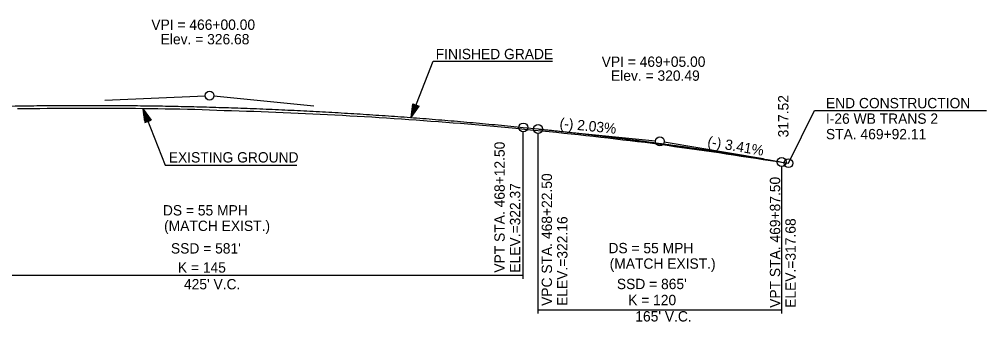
# Model space of a CAD drawing. Extents: x 69 to 2003113, y 512 to 837401.
# Drawn here: x 1924834 to 1925489, y 831485 to 831689 of the extents above; entities that cross this region are included whole.
import ezdxf

# ---------------------------------------------------------------- set-up
doc = ezdxf.new("R2010")
doc.units = 0
for name, color, linetype in [('BR_CENTER LINE BASELINE', 7, 'Continuous'), ('BR_CONCRETE', 7, 'Continuous'), ('BR_GRID DOTS', 7, 'Continuous'), ('BR_GRID LINES', 7, 'Continuous'), ('BR_TEXT', 7, 'Continuous'), ('RD_PD_ALT1_TrvlWay', 7, 'Continuous'), ('RD_SHT_IplotShp', 7, 'Continuous')]:
    doc.layers.add(name, color=color, linetype=linetype)

msp = doc.modelspace()

# ---------------------------------------------------------------- linework, layer by layer
at = {"layer": 'BR_CENTER LINE BASELINE'}
for p, q in [((1924892.19, 831634.52), (1924960.13, 831637.56)), ((1925033.76, 831630.53), (1924966.11, 831637.39)), ((1925197.49, 831613.92), (1925265.14, 831607.05)), ((1925338.11, 831594.82), (1925271.08, 831606.24))]:
    msp.add_line(p, q, dxfattribs=at)
for centre in [(1924963.12, 831637.7), (1925268.12, 831606.75), (1925355.23, 831591.9)]:
    msp.add_circle(centre, 3, dxfattribs=at)
at = {"layer": 'BR_GRID DOTS'}
for p, q in [((1925175.62, 831513.63), (1925175.62, 831613.13)), ((1925185.62, 831490.19), (1925185.62, 831612.12)), ((1925350.62, 831490.19), (1925350.62, 831589.69)), ((1924750.62, 831516.13), (1925175.62, 831516.13)), ((1925185.62, 831492.69), (1925350.62, 831492.69))]:
    msp.add_line(p, q, dxfattribs=at)
msp.add_lwpolyline([(1925355.19, 831591.9), (1925372.79, 831627.51), (1925489.44, 831627.51)], dxfattribs=at)
for centre in [(1925175.62, 831616.13), (1925185.62, 831615.12), (1925350.62, 831592.69)]:
    msp.add_circle(centre, 3, dxfattribs=at)
at = {"layer": 'BR_GRID LINES'}
for p, q in [((1925175.62, 831616.13), (1925185.62, 831615.12)), ((1925350.62, 831592.69), (1925355.23, 831591.9))]:
    msp.add_line(p, q, dxfattribs=at)
for points in [[(1924750.62, 831628.18), (1924759.12, 831628.54), (1924767.62, 831628.89), (1924776.12, 831629.21), (1924784.62, 831629.5), (1924793.12, 831629.77), (1924801.62, 831630.01), (1924810.12, 831630.23), (1924818.62, 831630.43), (1924827.12, 831630.6), (1924835.62, 831630.74), (1924844.12, 831630.86), (1924852.62, 831630.96), (1924861.12, 831631.03), (1924869.62, 831631.07), (1924878.12, 831631.09), (1924886.62, 831631.09), (1924895.12, 831631.06), (1924903.62, 831631), (1924912.12, 831630.92), (1924920.62, 831630.82), (1924929.12, 831630.69), (1924937.62, 831630.54), (1924946.12, 831630.36), (1924954.62, 831630.15), (1924963.12, 831629.93), (1924971.62, 831629.67), (1924980.12, 831629.39), (1924988.62, 831629.09), (1924997.12, 831628.76), (1925005.62, 831628.41), (1925014.12, 831628.03), (1925022.62, 831627.63), (1925031.12, 831627.2), (1925039.62, 831626.75), (1925048.12, 831626.27), (1925056.62, 831625.77), (1925065.12, 831625.24), (1925073.62, 831624.69), (1925082.12, 831624.12), (1925090.62, 831623.52), (1925099.12, 831622.89), (1925107.62, 831622.24), (1925116.12, 831621.56), (1925124.62, 831620.86), (1925133.12, 831620.14), (1925141.62, 831619.38), (1925150.12, 831618.61), (1925158.62, 831617.81), (1925167.12, 831616.98), (1925175.62, 831616.13)], [(1925185.62, 831615.12), (1925188.92, 831614.78), (1925192.22, 831614.44), (1925195.52, 831614.09), (1925198.82, 831613.74), (1925202.12, 831613.39), (1925205.42, 831613.03), (1925208.72, 831612.66), (1925212.02, 831612.29), (1925215.32, 831611.92), (1925218.62, 831611.54), (1925221.92, 831611.16), (1925225.22, 831610.77), (1925228.52, 831610.38), (1925231.82, 831609.99), (1925235.12, 831609.58), (1925238.42, 831609.18), (1925241.72, 831608.77), (1925245.02, 831608.35), (1925248.32, 831607.94), (1925251.62, 831607.51), (1925254.92, 831607.08), (1925258.22, 831606.65), (1925261.52, 831606.21), (1925264.82, 831605.77), (1925268.12, 831605.33), (1925271.42, 831604.88), (1925274.72, 831604.42), (1925278.02, 831603.96), (1925281.32, 831603.5), (1925284.62, 831603.03), (1925287.92, 831602.55), (1925291.22, 831602.07), (1925294.52, 831601.59), (1925297.82, 831601.1), (1925301.12, 831600.61), (1925304.42, 831600.12), (1925307.72, 831599.62), (1925311.02, 831599.11), (1925314.32, 831598.6), (1925317.62, 831598.09), (1925320.92, 831597.57), (1925324.22, 831597.04), (1925327.52, 831596.51), (1925330.82, 831595.98), (1925334.12, 831595.44), (1925337.42, 831594.9), (1925340.72, 831594.36), (1925344.02, 831593.8), (1925347.32, 831593.25), (1925350.62, 831592.69)]]:
    msp.add_spline(points, degree=3, dxfattribs=at)
at = {"layer": 'BR_TEXT'}
for points in [[(1924833.08, 831628.85), (1924838.08, 831628.93), (1924843.08, 831628.97), (1924848.08, 831629.06), (1924853.08, 831629.12), (1924858.08, 831629.15), (1924863.08, 831629.13), (1924868.08, 831629.12), (1924873.08, 831629.13), (1924878.08, 831629.18), (1924883.08, 831629.21), (1924888.08, 831629.19), (1924893.08, 831629.15), (1924898.08, 831629.12), (1924903.08, 831629.13), (1924908.08, 831629.11), (1924913.08, 831629.08), (1924918.08, 831629.04), (1924923.08, 831628.97), (1924928.08, 831628.86), (1924933.08, 831628.8), (1924938.08, 831628.76), (1924943.08, 831628.7), (1924948.08, 831628.58), (1924953.08, 831628.45), (1924958.08, 831628.31), (1924963.08, 831628.12), (1924968.08, 831627.89), (1924973.08, 831627.66), (1924978.08, 831627.62), (1924983.08, 831627.41), (1924988.08, 831627.24), (1924993.08, 831627.08), (1924998.08, 831626.91)], [(1924998.08, 831626.91), (1925003.08, 831626.75), (1925008.08, 831626.54), (1925013.08, 831626.3), (1925018.08, 831626.08), (1925023.08, 831625.83), (1925028.08, 831625.58), (1925033.08, 831625.33), (1925038.08, 831625.09), (1925043.08, 831624.85), (1925048.08, 831624.61), (1925053.08, 831624.35), (1925058.08, 831624.08), (1925063.08, 831623.8), (1925068.08, 831623.52), (1925073.08, 831623.26), (1925078.08, 831622.94), (1925083.08, 831622.6), (1925088.08, 831622.25), (1925093.08, 831621.91), (1925098.08, 831621.58), (1925103.08, 831621.21), (1925108.08, 831620.84), (1925113.08, 831620.45), (1925118.08, 831620.07), (1925123.08, 831619.69), (1925128.08, 831619.36), (1925133.08, 831618.96), (1925138.08, 831618.55), (1925143.08, 831618.1), (1925148.08, 831617.63), (1925153.08, 831617.16), (1925158.08, 831616.71), (1925163.08, 831616.27), (1925168.08, 831615.79), (1925173.08, 831615.3), (1925178.08, 831614.81), (1925183.08, 831614.37), (1925188.08, 831613.88), (1925193.08, 831613.39), (1925198.08, 831612.87), (1925203.08, 831612.34), (1925208.08, 831611.82), (1925213.08, 831611.24), (1925218.08, 831610.66), (1925223.08, 831610.14), (1925228.08, 831609.62), (1925233.08, 831609.09), (1925238.08, 831608.44), (1925243.08, 831607.78), (1925248.08, 831607.19), (1925253.08, 831606.69), (1925258.08, 831606.12), (1925263.08, 831605.41), (1925268.08, 831604.7), (1925273.08, 831604.02), (1925278.08, 831603.32), (1925283.08, 831602.63), (1925288.08, 831601.94), (1925293.08, 831601.24), (1925298.08, 831600.55), (1925303.08, 831599.82), (1925308.08, 831599.08), (1925313.08, 831598.31), (1925318.08, 831597.54), (1925323.08, 831596.77), (1925328.08, 831596), (1925333.08, 831595.26), (1925338.08, 831594.52), (1925343.08, 831593.76), (1925348.08, 831593.01), (1925353.08, 831592.22), (1925355.19, 831591.9)]]:
    msp.add_lwpolyline(points, dxfattribs=at)
at = {"layer": 'RD_PD_ALT1_TrvlWay'}
for p, q in [((1925099.7, 831622.94), (1925114.66, 831660.9)), ((1925114.66, 831660.9), (1925195.44, 831660.9)), ((1925099.7, 831622.94), (1925100.91, 831632.14)), ((1925100.91, 831632.14), (1925105.09, 831630.49)), ((1924918.08, 831628.6), (1924933.04, 831590.65)), ((1924921.38, 831620.23), (1924918.08, 831628.6)), ((1924918.08, 831628.6), (1924923.48, 831621.05)), ((1924918.08, 831628.6), (1924919.29, 831619.4)), ((1925103, 831631.31), (1925099.7, 831622.94)), ((1925099.7, 831622.94), (1925105.09, 831630.49)), ((1924919.29, 831619.4), (1924923.48, 831621.05)), ((1924933.04, 831590.65), (1925022.23, 831590.65))]:
    msp.add_line(p, q, dxfattribs=at)
for points in [[(1925102.9, 831631.23), (1925099.82, 831623.44), (1925102.87, 831631.31), (1925099.9, 831623.83), (1925102.77, 831631.31), (1925099.92, 831624.1), (1925102.65, 831631.33), (1925099.95, 831624.43), (1925102.57, 831631.38), (1925100.03, 831624.92), (1925102.46, 831631.45), (1925100.11, 831625.45), (1925102.34, 831631.45), (1925100.17, 831625.84), (1925102.26, 831631.5), (1925100.23, 831626.3), (1925102.16, 831631.49), (1925100.29, 831626.7), (1925102.1, 831631.59), (1925100.32, 831627.04), (1925101.96, 831631.6), (1925100.38, 831627.54), (1925101.86, 831631.66), (1925100.5, 831628.14), (1925101.77, 831631.72), (1925100.5, 831628.56), (1925101.66, 831631.76), (1925100.59, 831629.18), (1925101.55, 831631.77), (1925100.68, 831629.68), (1925101.44, 831631.87), (1925100.74, 831630.12), (1925101.34, 831631.87), (1925100.78, 831630.53), (1925101.26, 831631.96), (1925100.85, 831631.02), (1925101.15, 831631.92), (1925100.93, 831631.57), (1925101.03, 831631.93)], [(1924921.28, 831620.31), (1924918.21, 831628.11), (1924921.25, 831620.24), (1924918.28, 831627.71), (1924921.15, 831620.24), (1924918.31, 831627.44), (1924921.04, 831620.21), (1924918.34, 831627.12), (1924920.96, 831620.16), (1924918.41, 831626.62), (1924920.84, 831620.1), (1924918.5, 831626.1), (1924920.73, 831620.09), (1924918.55, 831625.7), (1924920.65, 831620.04), (1924918.61, 831625.24), (1924920.54, 831620.06), (1924918.67, 831624.85), (1924920.48, 831619.95), (1924918.71, 831624.5), (1924920.34, 831619.94), (1924918.76, 831624), (1924920.25, 831619.88), (1924918.88, 831623.41), (1924920.15, 831619.82), (1924918.88, 831622.99), (1924920.05, 831619.78), (1924918.97, 831622.36), (1924919.93, 831619.78), (1924919.07, 831621.86), (1924919.83, 831619.68), (1924919.12, 831621.42), (1924919.73, 831619.68), (1924919.16, 831621.02), (1924919.64, 831619.59), (1924919.23, 831620.52), (1924919.53, 831619.62), (1924919.31, 831619.97), (1924919.41, 831619.61)], [(1924918.36, 831628.08), (1924921.4, 831620.36), (1924918.52, 831627.83), (1924921.51, 831620.4), (1924918.67, 831627.59), (1924921.59, 831620.39), (1924918.85, 831627.38), (1924921.65, 831620.44), (1924919.06, 831627.12), (1924921.74, 831620.45), (1924919.23, 831626.87), (1924921.81, 831620.48), (1924919.45, 831626.57), (1924921.91, 831620.5), (1924919.69, 831626.21), (1924922.02, 831620.56), (1924919.9, 831625.89), (1924922.1, 831620.55), (1924920.13, 831625.56), (1924922.18, 831620.61), (1924920.37, 831625.26), (1924922.27, 831620.64), (1924920.61, 831624.91), (1924922.32, 831620.72), (1924920.93, 831624.45), (1924922.42, 831620.72), (1924921.16, 831624.17), (1924922.5, 831620.71), (1924921.45, 831623.78), (1924922.58, 831620.78), (1924921.69, 831623.37), (1924922.67, 831620.84), (1924921.92, 831623.06), (1924922.76, 831620.93), (1924922.17, 831622.78), (1924922.83, 831620.96), (1924922.45, 831622.31), (1924922.97, 831620.94), (1924922.64, 831622.05), (1924923.11, 831620.99), (1924922.82, 831621.88), (1924923.22, 831621.13), (1924923.34, 831621.08), (1924923.18, 831621.12)], [(1925099.97, 831623.46), (1925103.02, 831631.19), (1925100.13, 831623.72), (1925103.12, 831631.14), (1925100.29, 831623.96), (1925103.2, 831631.15), (1925100.47, 831624.16), (1925103.27, 831631.11), (1925100.67, 831624.42), (1925103.36, 831631.09), (1925100.85, 831624.67), (1925103.43, 831631.06), (1925101.07, 831624.97), (1925103.52, 831631.05), (1925101.31, 831625.33), (1925103.64, 831630.98), (1925101.52, 831625.65), (1925103.72, 831630.99), (1925101.75, 831625.98), (1925103.8, 831630.94), (1925101.99, 831626.29), (1925103.89, 831630.9), (1925102.22, 831626.64), (1925103.94, 831630.82), (1925102.54, 831627.09), (1925104.04, 831630.82), (1925102.78, 831627.38), (1925104.12, 831630.83), (1925103.07, 831627.76), (1925104.19, 831630.76), (1925103.31, 831628.17), (1925104.29, 831630.7), (1925103.53, 831628.48), (1925104.37, 831630.61), (1925103.78, 831628.76), (1925104.44, 831630.58), (1925104.07, 831629.23), (1925104.59, 831630.61), (1925104.25, 831629.5), (1925104.73, 831630.55), (1925104.44, 831629.66), (1925104.83, 831630.41), (1925104.95, 831630.46), (1925104.8, 831630.42)]]:
    msp.add_lwpolyline(points, dxfattribs=at)

# ---------------------------------------------------------------- texts
at = {"layer": 'BR_CENTER LINE BASELINE'}
for s, rotation, p in [('(-) 2.03%', 354.2061, (1925199.96, 831615.67)), ('(-) 3.41%', 350.32936, (1925299.97, 831603.35))]:
    msp.add_text(s, height=7, rotation=rotation, dxfattribs=at).set_placement(p)
at = {"layer": 'BR_CONCRETE'}
for s, p in [('VPT STA. 468+12.50 ', (1925163.05, 831517.77)), ('VPC STA. 468+22.50 ', (1925195.05, 831495.27)), ('VPT STA. 469+87.50 ', (1925349.62, 831493.96)), ('ELEV.=322.37', (1925173.55, 831517.77)), ('ELEV.=322.16', (1925205.55, 831495.27)), ('ELEV.=317.68', (1925360.12, 831493.96))]:
    msp.add_text(s, height=7, rotation=90, dxfattribs=at).set_placement(p)
at = {"layer": 'BR_GRID DOTS'}
for s, p in [('DS = 55 MPH', (1924931.53, 831556.51)), ('(MATCH EXIST.)', (1924932.33, 831546.01)), ("SSD = 581'", (1924936.98, 831530.74)), ('DS = 55 MPH', (1925233.29, 831530.93)), ('(MATCH EXIST.)', (1925234.1, 831520.43)), ('K = 145', (1924941.67, 831517.79)), ("425' V.C.", (1924945.81, 831506.47)), ("SSD = 865'", (1925239, 831506.62)), ('K = 120', (1925246.63, 831495.77)), ("165' V.C.", (1925251.48, 831484.71))]:
    msp.add_text(s, height=7, dxfattribs=at).set_placement(p)
at = {"layer": 'RD_PD_ALT1_TrvlWay'}
for s, p in [('FINISHED GRADE', (1925116.3, 831662.36)), ('EXISTING GROUND', (1924935.51, 831592.38))]:
    msp.add_text(s, height=7, dxfattribs=at).set_placement(p)
at = {"layer": 'RD_SHT_IplotShp'}
for s, p in [('VPI = 466+00.00', (1924923.7, 831682.22)), ('Elev. = 326.68', (1924930.02, 831672.4)), ('VPI = 469+05.00', (1925228.7, 831657.16)), ('Elev. = 320.49', (1925235.03, 831647.73)), ('END CONSTRUCTION ', (1925380.59, 831629.1)), ('I-26 WB TRANS 2', (1925380.59, 831618.6)), ('STA. 469+92.11', (1925380.59, 831608.1))]:
    msp.add_text(s, height=7, dxfattribs=at).set_placement(p)
msp.add_text('317.52', height=7, rotation=90, dxfattribs=at).set_placement((1925355.23, 831609.4))

doc.saveas('drawing.dxf')
